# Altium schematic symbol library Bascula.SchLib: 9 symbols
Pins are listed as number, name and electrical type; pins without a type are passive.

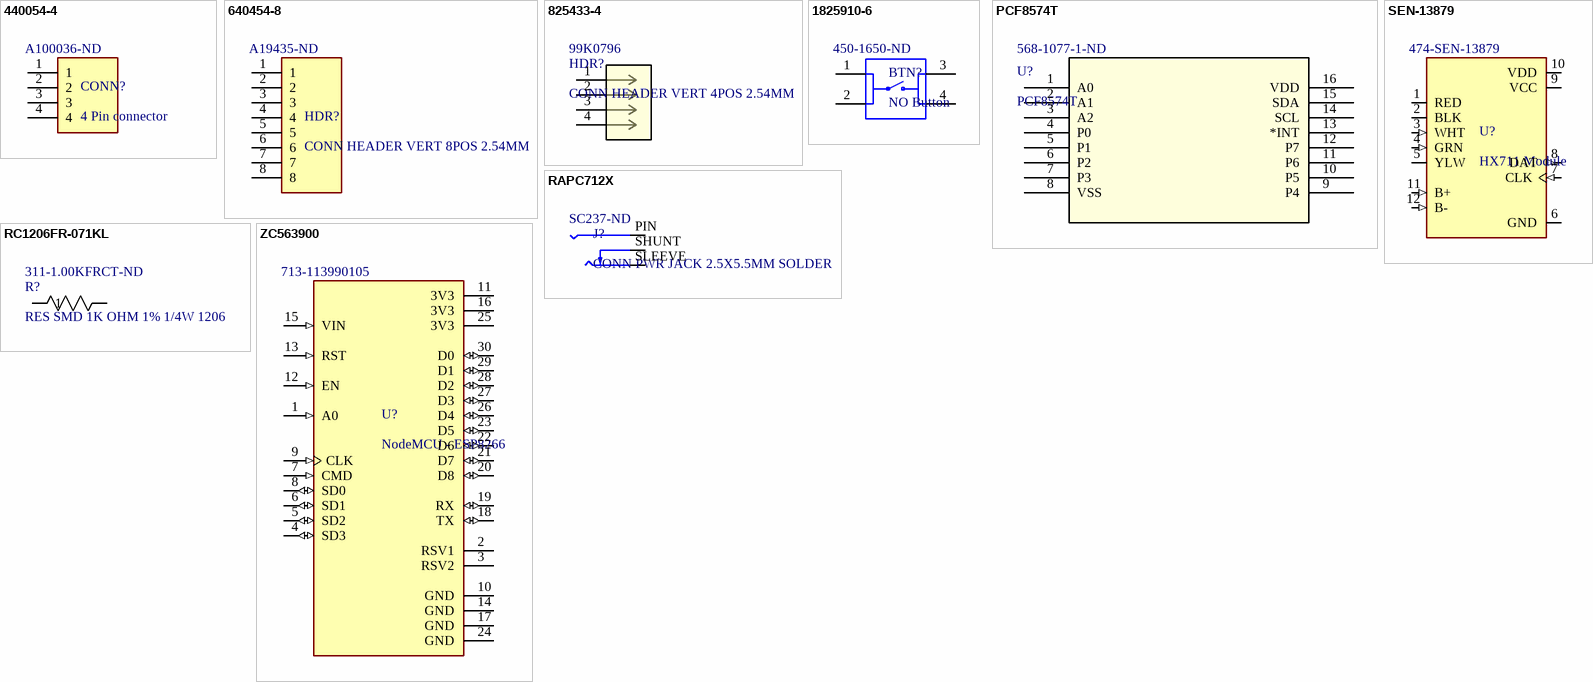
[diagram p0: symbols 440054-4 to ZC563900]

## 440054-4
designator CONN?, comment 4 Pin connector  Supplier Part Number 1: A100036-ND
Cabezal de conector Orificio pasante 4 posiciones 0.079" (2.00mm). / Complementario con 1735447-4.; MF: TE Connectivity; MP: 440054-4
footprint 440054-4 (4 pin male connector for PCB)
pins: 1, 2, 3, 4

## 640454-8
designator HDR?, comment CONN HEADER VERT 8POS 2.54MM  Supplier Part Number 1: A19435-ND
Cabezal de conector Orificio pasante 8 posiciones 0.100" (2.54mm). / Complementario con 3-644540-8.; MP: 640454-8; MF: TE Connectivity; Underplate Material: Nickel; Number of Contacts: 8; Connector Type: Plug,Header,Pin; Mating Alignment: No (Without); Current Rating: 5A; Max Voltage Rating (AC): 250V; Connector System: Wire-to-Board; PCB Mount Retention: Without; Contact Resistance: 6mR; PCB Mounting Orientation: Vertical; Contact Style: Straight; Plating Thickness: 3.81um; PCB Thickness: 0.063inch; Contact Post Length: 3.56mm; Approvals: CSA
footprint 640454-8 (8 pin male header connector 2.54MM)
pins: 1, 2, 3, 4, 5, 6, 7, 8

## 825433-4
designator HDR?, comment CONN HEADER VERT 4POS 2.54MM  Supplier Part Number 1: 99K0796
Cabezal de conector Orificio pasante 4 posiciones 0.100" (2.54mm); Manufacturer_Part_Number: 825433-4; MF: TE Connectivity; Description: CONN HEADER 4POS VERT GOLD; Number of Positions: 4; Connector Type: Plug,Header,Pin; Gender: Male; Current Rating: 3A; Board Standoff: No (Without); High Speed Serial Data Connector: No; PCB Mount Retention: Without; PCB Mounting Orientation: Vertical; Contact Current Rating: 5A; Contact Post Length: 0.1259inch; Plating Thickness: 2.5um; Approvals: CSA
footprint 825433-4 (HDR_1X4_0.100")
pins: 1, 2, 3, 4

## 1825910-6
designator BTN?, comment NO Button  Supplier Part Number 1: 450-1650-ND
Interruptores táctiles SPST-NO (Normalmente abierto) Activación superior Orificio pasante. SWITCH TACTILE SPST-NO 0.05A 24V; Configuration_Pole-Throw: Single Pole - Single Throw; MF: TE Connectivity; Contact_Current_Rating: 50 mA; MP: 1825910-6
footprint 1825910-6 (NO Button)
pins: 1, 2, 3, 4

## PCF8574T
designator U?  Supplier Part Number 1: 568-1077-1-ND
Expansores de E/S 8 I²C 100 kHz 16-SO.; Manufacturer: NXP Semiconductors; Manufacturer Part Number: PCF8574T/3,518; MF: NXP; MP: PCF8574T/3; Number of I/Os: 8; Min Supply Voltage: 2.5V; Max Supply Voltage: 6V; Interface: I2C; Nominal Supply Current: 100mA; Max Frequency: 100kHz; Output Current: 25mA; Max Power Dissipation: 400mW; Number of Ports: 1
footprint PCF8574T (IC Expansor ES)
pins: 1 A0, 2 A1, 3 A2, 4 P0, 5 P1, 6 P2, 7 P3, 8 VSS, 9 P4, 10 P5, 11 P6, 12 P7, 13 *INT, 14 SCL, 15 SDA, 16 VDD

## RAPC712X
designator J?, comment CONN PWR JACK 2.5X5.5MM SOLDER  Supplier Part Number 1: SC237-ND
Conn DC Power PL 2 POS Solder RA Thru-Hole 3 Terminal 1 Port Bulk; MF: Switchcraft; MP: RAPC712X; Number of Terminals/Pins: 3; Body Material: Thermoplastic; Gender: Male; Shielding: Unshielded; Current Rating: 5A; Connector Type: Jack,Power; Insulation Resistance: 30MR; Number of Ports: 1; Number of Contacts: 2; Pin Diameter: 2.5mm
footprint RAPC712X (Power Jack Barrel TH)
pins: PIN, SHUNT, SLEEVE

## RC1206FR-071KL
designator R?, comment RES SMD 1K OHM 1% 1/4W 1206  Supplier Part Number 1: 311-1.00KFRCT-ND
1 kOhms ±1% 0.25W, 1/4W Resistencia en microprocesador 1206 (3216 métrico) Resistente a la humedad Película gruesa; MN: Yageo; MP: RC1206FR-071KL; Resistance: 1kR; Temperature Coefficient: 100ppm/°C; Power Rating: 250mW; Voltage Rating: 200V
footprint RES_RC1206_YAG (1k SMD res 3216)
pins: 1, 2

## SEN-13879
designator U?, comment HX711 Module  Supplier Part Number 1: 474-SEN-13879
Precision 24-bit analogto-digital converter (ADC) designed for weigh / scales and industrial control  pplications to interface directly with a bridge sensor. Breakout module.; Manufacturer_Part_Number: SEN-13879; Manufacturer_Name: SparkFun
footprint SPARKFUN_SEN-13879
pins: 1 RED (io), 2 BLK (io), 3 WHT (in), 4 GRN (in), 5 YLW (io), 6 GND (power), 7 CLK (in), 8 DAT (out), 9 VCC (power), 10 VDD (power), 11 B+ (in), 12 B- (in)

## ZC563900
designator U?, comment NodeMCU - ESP8266  Supplier Part Number 1: 713-113990105
NodeMcu Lua ESP8266 WIFI Internet of Things Network Development Module Board; Manufacturer_Part_Number: ZC563900; Manufacturer_Name: YKS
footprint ZC563900 (NodeMCU ESP8266)
pins: 1 A0 (in), 2 RSV1, 3 RSV2, 4 SD3 (io), 5 SD2 (io), 6 SD1 (io), 7 CMD (in), 8 SD0 (io), 9 CLK (in), 10 GND (power), 11 3V3 (power), 12 EN (in), 13 RST (in), 14 GND (power), 15 VIN (in), 16 3V3 (power), 17 GND (power), 18 TX (io), 19 RX (io), 20 D8 (io), 21 D7 (io), 22 D6 (io), 23 D5 (io), 24 GND (power), 25 3V3 (power), 26 D4 (io), 27 D3 (io), 28 D2 (io), 29 D1 (io), 30 D0 (io)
